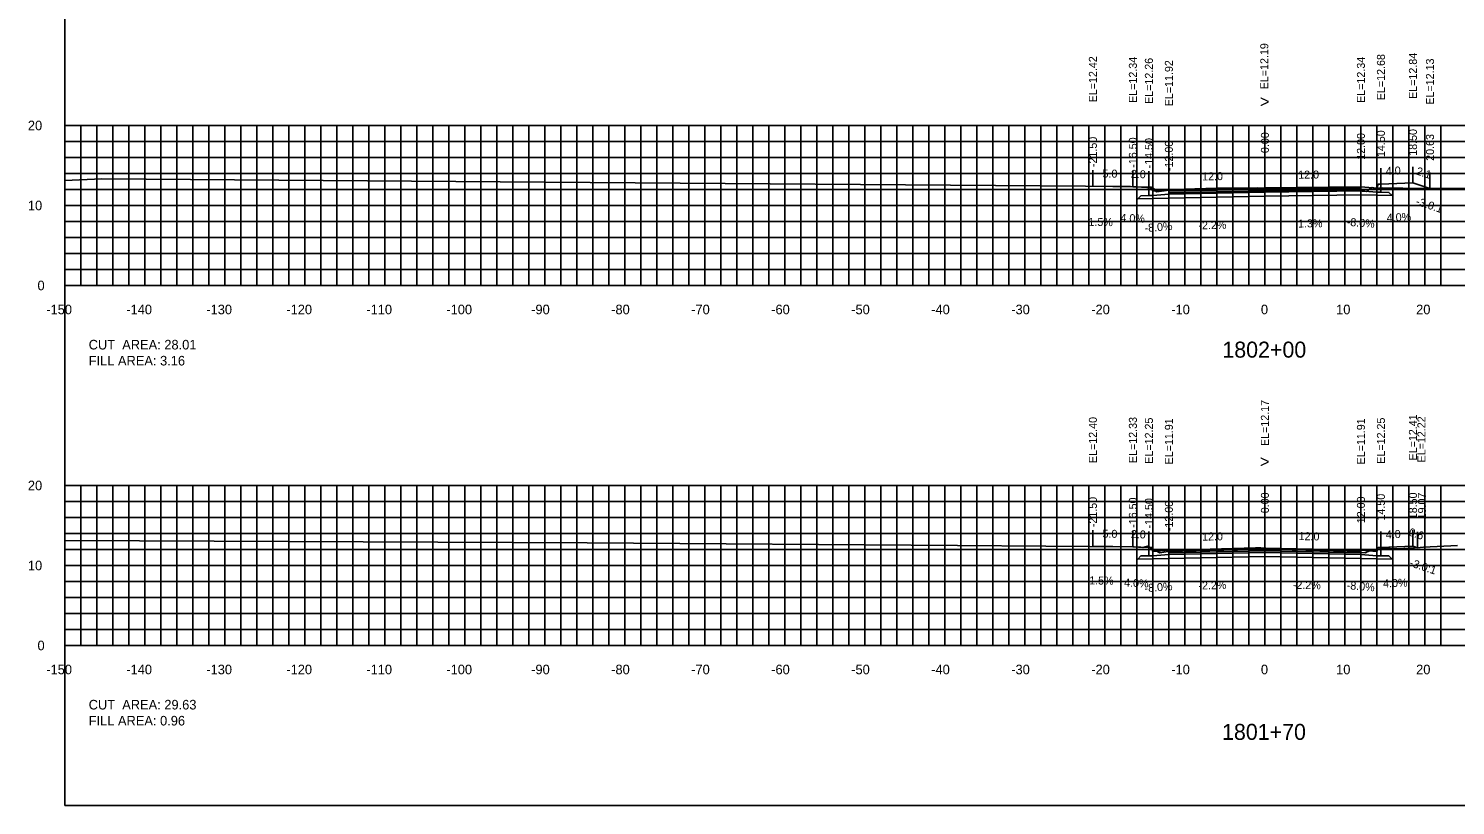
# Model space of a CAD drawing. Extents: x 1797759 to 1802785, y 249826 to 250371.
# Drawn here: x 1802136.5 to 1802314.8, y 250079.4 to 250176.5 of the extents above; entities that cross this region are included whole.
import ezdxf

# ---------------------------------------------------------------- set-up
doc = ezdxf.new("R2010")
doc.units = 0
for name, color, linetype in [('29', 7, 'Continuous'), ('AXIS', 7, 'Continuous'), ('great seal', 7, 'Continuous'), ('Level 1', 7, 'Continuous'), ('Level 10', 7, 'Continuous'), ('Level 13', 7, 'Continuous'), ('Level 15', 7, 'Continuous'), ('Level 30', 7, 'Continuous'), ('Level 40', 7, 'Continuous'), ('Level 45', 7, 'Continuous'), ('Level 63', 7, 'Continuous'), ('Level 7', 7, 'Continuous'), ('LS-SURVEY POINT', 7, 'Continuous'), ('PIPE', 7, 'Continuous'), ('TOPO', 7, 'Continuous')]:
    doc.layers.add(name, color=color, linetype=linetype)

msp = doc.modelspace()

# ---------------------------------------------------------------- linework, layer by layer
at = {"layer": '29'}
for points in [[(1802279, 250156.21), (1802291, 250156.47), (1802303, 250156.62), (1802303, 250156.43), (1802291, 250156.28), (1802279, 250156.02)], [(1802279, 250111.19), (1802291, 250111.45), (1802303, 250111.19), (1802303, 250111), (1802291, 250111.26), (1802279, 250111)]]:
    msp.add_lwpolyline(points, close=True, dxfattribs=at)
at = {"layer": 'AXIS'}
for p, q in [((1802269.5, 250156.85), (1802269.5, 250158.85)), ((1802274.5, 250156.78), (1802274.5, 250158.78)), ((1802276.5, 250156.7), (1802276.5, 250158.7)), ((1802291, 250156.62), (1802291, 250158.62)), ((1802303, 250156.77), (1802303, 250158.77)), ((1802305.5, 250157.11), (1802305.5, 250159.11)), ((1802309.5, 250157.27), (1802309.5, 250159.27)), ((1802311.63, 250156.56), (1802311.63, 250158.56)), ((1802279, 250156.36), (1802279, 250158.36)), ((1802269.5, 250111.83), (1802269.5, 250113.83)), ((1802274.5, 250111.76), (1802274.5, 250113.76)), ((1802276.5, 250111.68), (1802276.5, 250113.68)), ((1802279, 250111.34), (1802279, 250113.34)), ((1802291, 250111.6), (1802291, 250113.6)), ((1802303, 250111.34), (1802303, 250113.34)), ((1802305.5, 250111.68), (1802305.5, 250113.68)), ((1802309.5, 250111.84), (1802309.5, 250113.84)), ((1802310.07, 250111.65), (1802310.07, 250113.65))]:
    msp.add_line(p, q, dxfattribs=at)
for points in [[(1802141, 250079.43), (1802441, 250079.43), (1802441, 250269.43), (1802141, 250269.43)], [(1802303, 250156.77), (1802305, 250156.61), (1802305.17, 250157.11), (1802305.5, 250157.11), (1802305.5, 250156.08), (1802305, 250156.08), (1802303, 250156.24)], [(1802279, 250156.36), (1802277, 250156.2), (1802276.83, 250156.7), (1802276.5, 250156.7), (1802276.5, 250155.67), (1802277, 250155.67), (1802279, 250155.83)], [(1802279, 250111.34), (1802277, 250111.18), (1802276.83, 250111.68), (1802276.5, 250111.68), (1802276.5, 250110.65), (1802277, 250110.65), (1802279, 250110.81)], [(1802303, 250111.34), (1802305, 250111.18), (1802305.17, 250111.68), (1802305.5, 250111.68), (1802305.5, 250110.65), (1802305, 250110.65), (1802303, 250110.81)]]:
    msp.add_lwpolyline(points, close=True, dxfattribs=at)
at = {"layer": 'great seal'}
for points in [[(1802141, 250157.56), (1802145.63, 250157.77), (1802195.44, 250157.4), (1802274.2, 250156.82), (1802275.56, 250156.72), (1802276.24, 250156.66), (1802277.05, 250156.61), (1802277.14, 250156.51), (1802277.45, 250156.13), (1802278.42, 250156.26), (1802279.52, 250156.42), (1802284.96, 250156.58), (1802290.06, 250156.64), (1802302.07, 250156.3), (1802302.17, 250156.3), (1802303.67, 250156.19), (1802303.7, 250156.19), (1802303.77, 250156.24), (1802304.25, 250156.58), (1802304.41, 250156.66), (1802304.86, 250156.61), (1802305.68, 250156.64), (1802310.81, 250156.54), (1802311.15, 250156.54), (1802311.65, 250156.56), (1802319.58, 250156.58)], [(1802141, 250112.56), (1802206.29, 250112.27), (1802252.58, 250111.93), (1802274.67, 250111.77), (1802275.73, 250111.69), (1802276.32, 250111.84), (1802277.86, 250111.03), (1802277.87, 250111.03), (1802277.87, 250111.03), (1802279.89, 250111.33), (1802289.83, 250111.63), (1802290.02, 250111.64), (1802290.48, 250111.62), (1802291.12, 250111.6), (1802302.04, 250111.2), (1802303.09, 250111.06), (1802303.56, 250111.01), (1802303.86, 250111.16), (1802303.92, 250111.19), (1802304.13, 250111.26), (1802304.33, 250111.27), (1802305.51, 250111.52), (1802306.31, 250111.53), (1802306.48, 250111.54), (1802306.67, 250111.54), (1802307.59, 250111.52), (1802307.64, 250111.52), (1802310.4, 250111.67), (1802310.84, 250111.71), (1802315.08, 250111.93)]]:
    msp.add_lwpolyline(points, dxfattribs=at)
at = {"layer": 'Level 1'}
for points in [[(1802269.5, 250156.85), (1802274.5, 250156.78), (1802276.5, 250156.7), (1802276.83, 250156.7), (1802277, 250156.2), (1802279, 250156.36), (1802291, 250156.62), (1802303, 250156.77), (1802305, 250156.61), (1802305.17, 250157.11), (1802305.5, 250157.11), (1802309.5, 250157.27), (1802311.63, 250156.56)], [(1802269.5, 250111.83), (1802274.5, 250111.76), (1802276.5, 250111.68), (1802276.83, 250111.68), (1802277, 250111.18), (1802279, 250111.34), (1802291, 250111.6), (1802303, 250111.34), (1802305, 250111.18), (1802305.17, 250111.68), (1802305.5, 250111.68), (1802309.5, 250111.84), (1802310.07, 250111.65)]]:
    msp.add_lwpolyline(points, dxfattribs=at)
at = {"layer": 'Level 13'}
for points in [[(1802303, 250155.74), (1802306.9, 250155.66), (1802306.5, 250156.06), (1802305.5, 250156.08), (1802305, 250156.08), (1802303, 250156.24), (1802291, 250156.09), (1802279, 250155.83), (1802277, 250155.67), (1802276.5, 250155.67), (1802275.5, 250155.64), (1802275.1, 250155.24), (1802279, 250155.33), (1802291, 250155.59)], [(1802303, 250110.31), (1802306.9, 250110.22), (1802306.5, 250110.63), (1802305.5, 250110.65), (1802305, 250110.65), (1802303, 250110.81), (1802291, 250111.07), (1802279, 250110.81), (1802277, 250110.65), (1802276.5, 250110.65), (1802275.5, 250110.63), (1802275.1, 250110.22), (1802279, 250110.31), (1802291, 250110.57)]]:
    msp.add_lwpolyline(points, close=True, dxfattribs=at)
at = {"layer": 'Level 15'}
for p, q in [((1802141, 250164.43), (1802441, 250164.43)), ((1802141, 250144.43), (1802141, 250164.43)), ((1802143, 250144.43), (1802143, 250164.43)), ((1802145, 250144.43), (1802145, 250164.43)), ((1802147, 250144.43), (1802147, 250164.43)), ((1802149, 250144.43), (1802149, 250164.43)), ((1802151, 250144.43), (1802151, 250164.43)), ((1802153, 250144.43), (1802153, 250164.43)), ((1802155, 250144.43), (1802155, 250164.43)), ((1802157, 250144.43), (1802157, 250164.43)), ((1802159, 250144.43), (1802159, 250164.43)), ((1802161, 250144.43), (1802161, 250164.43)), ((1802163, 250144.43), (1802163, 250164.43)), ((1802165, 250144.43), (1802165, 250164.43)), ((1802167, 250144.43), (1802167, 250164.43)), ((1802169, 250144.43), (1802169, 250164.43)), ((1802171, 250144.43), (1802171, 250164.43)), ((1802173, 250144.43), (1802173, 250164.43)), ((1802175, 250144.43), (1802175, 250164.43)), ((1802177, 250144.43), (1802177, 250164.43)), ((1802179, 250144.43), (1802179, 250164.43)), ((1802181, 250144.43), (1802181, 250164.43)), ((1802183, 250144.43), (1802183, 250164.43)), ((1802185, 250144.43), (1802185, 250164.43)), ((1802187, 250144.43), (1802187, 250164.43)), ((1802189, 250144.43), (1802189, 250164.43)), ((1802191, 250144.43), (1802191, 250164.43)), ((1802193, 250144.43), (1802193, 250164.43)), ((1802195, 250144.43), (1802195, 250164.43)), ((1802197, 250144.43), (1802197, 250164.43)), ((1802199, 250144.43), (1802199, 250164.43)), ((1802201, 250144.43), (1802201, 250164.43)), ((1802203, 250144.43), (1802203, 250164.43)), ((1802205, 250144.43), (1802205, 250164.43)), ((1802207, 250144.43), (1802207, 250164.43)), ((1802209, 250144.43), (1802209, 250164.43)), ((1802211, 250144.43), (1802211, 250164.43)), ((1802213, 250144.43), (1802213, 250164.43)), ((1802215, 250144.43), (1802215, 250164.43)), ((1802217, 250144.43), (1802217, 250164.43)), ((1802219, 250144.43), (1802219, 250164.43)), ((1802221, 250144.43), (1802221, 250164.43)), ((1802223, 250144.43), (1802223, 250164.43)), ((1802225, 250144.43), (1802225, 250164.43)), ((1802227, 250144.43), (1802227, 250164.43)), ((1802229, 250144.43), (1802229, 250164.43)), ((1802231, 250144.43), (1802231, 250164.43)), ((1802233, 250144.43), (1802233, 250164.43)), ((1802235, 250144.43), (1802235, 250164.43)), ((1802237, 250144.43), (1802237, 250164.43)), ((1802239, 250144.43), (1802239, 250164.43)), ((1802241, 250144.43), (1802241, 250164.43)), ((1802243, 250144.43), (1802243, 250164.43)), ((1802245, 250144.43), (1802245, 250164.43)), ((1802247, 250144.43), (1802247, 250164.43)), ((1802249, 250144.43), (1802249, 250164.43)), ((1802251, 250144.43), (1802251, 250164.43)), ((1802253, 250144.43), (1802253, 250164.43)), ((1802255, 250144.43), (1802255, 250164.43)), ((1802257, 250144.43), (1802257, 250164.43)), ((1802259, 250144.43), (1802259, 250164.43)), ((1802261, 250144.43), (1802261, 250164.43)), ((1802263, 250144.43), (1802263, 250164.43)), ((1802265, 250144.43), (1802265, 250164.43)), ((1802267, 250144.43), (1802267, 250164.43)), ((1802269, 250144.43), (1802269, 250164.43)), ((1802271, 250144.43), (1802271, 250164.43)), ((1802273, 250144.43), (1802273, 250164.43)), ((1802275, 250144.43), (1802275, 250164.43)), ((1802277, 250144.43), (1802277, 250164.43)), ((1802279, 250144.43), (1802279, 250164.43)), ((1802281, 250144.43), (1802281, 250164.43)), ((1802283, 250144.43), (1802283, 250164.43)), ((1802285, 250144.43), (1802285, 250164.43)), ((1802287, 250144.43), (1802287, 250164.43)), ((1802289, 250144.43), (1802289, 250164.43)), ((1802291, 250144.43), (1802291, 250164.43)), ((1802293, 250144.43), (1802293, 250164.43)), ((1802295, 250144.43), (1802295, 250164.43)), ((1802297, 250144.43), (1802297, 250164.43)), ((1802299, 250144.43), (1802299, 250164.43)), ((1802301, 250144.43), (1802301, 250164.43)), ((1802303, 250144.43), (1802303, 250164.43)), ((1802305, 250144.43), (1802305, 250164.43)), ((1802307, 250144.43), (1802307, 250164.43)), ((1802309, 250144.43), (1802309, 250164.43)), ((1802311, 250144.43), (1802311, 250164.43)), ((1802313, 250144.43), (1802313, 250164.43)), ((1802141, 250162.43), (1802441, 250162.43)), ((1802141, 250160.43), (1802441, 250160.43)), ((1802141, 250158.43), (1802441, 250158.43)), ((1802141, 250156.43), (1802441, 250156.43)), ((1802141, 250154.43), (1802441, 250154.43)), ((1802141, 250152.43), (1802441, 250152.43)), ((1802141, 250150.43), (1802441, 250150.43)), ((1802141, 250148.43), (1802441, 250148.43)), ((1802141, 250146.43), (1802441, 250146.43)), ((1802141, 250144.43), (1802441, 250144.43)), ((1802141, 250119.43), (1802441, 250119.43)), ((1802141, 250099.43), (1802141, 250119.43)), ((1802143, 250099.43), (1802143, 250119.43)), ((1802145, 250099.43), (1802145, 250119.43)), ((1802147, 250099.43), (1802147, 250119.43)), ((1802149, 250099.43), (1802149, 250119.43)), ((1802151, 250099.43), (1802151, 250119.43)), ((1802153, 250099.43), (1802153, 250119.43)), ((1802155, 250099.43), (1802155, 250119.43)), ((1802157, 250099.43), (1802157, 250119.43)), ((1802159, 250099.43), (1802159, 250119.43)), ((1802161, 250099.43), (1802161, 250119.43)), ((1802163, 250099.43), (1802163, 250119.43)), ((1802165, 250099.43), (1802165, 250119.43)), ((1802167, 250099.43), (1802167, 250119.43)), ((1802169, 250099.43), (1802169, 250119.43)), ((1802171, 250099.43), (1802171, 250119.43)), ((1802173, 250099.43), (1802173, 250119.43)), ((1802175, 250099.43), (1802175, 250119.43)), ((1802177, 250099.43), (1802177, 250119.43)), ((1802179, 250099.43), (1802179, 250119.43)), ((1802181, 250099.43), (1802181, 250119.43)), ((1802183, 250099.43), (1802183, 250119.43)), ((1802185, 250099.43), (1802185, 250119.43)), ((1802187, 250099.43), (1802187, 250119.43)), ((1802189, 250099.43), (1802189, 250119.43)), ((1802191, 250099.43), (1802191, 250119.43)), ((1802193, 250099.43), (1802193, 250119.43)), ((1802195, 250099.43), (1802195, 250119.43)), ((1802197, 250099.43), (1802197, 250119.43)), ((1802199, 250099.43), (1802199, 250119.43)), ((1802201, 250099.43), (1802201, 250119.43)), ((1802203, 250099.43), (1802203, 250119.43)), ((1802205, 250099.43), (1802205, 250119.43)), ((1802207, 250099.43), (1802207, 250119.43)), ((1802209, 250099.43), (1802209, 250119.43)), ((1802211, 250099.43), (1802211, 250119.43)), ((1802213, 250099.43), (1802213, 250119.43)), ((1802215, 250099.43), (1802215, 250119.43)), ((1802217, 250099.43), (1802217, 250119.43)), ((1802219, 250099.43), (1802219, 250119.43)), ((1802221, 250099.43), (1802221, 250119.43)), ((1802223, 250099.43), (1802223, 250119.43)), ((1802225, 250099.43), (1802225, 250119.43)), ((1802227, 250099.43), (1802227, 250119.43)), ((1802229, 250099.43), (1802229, 250119.43)), ((1802231, 250099.43), (1802231, 250119.43)), ((1802233, 250099.43), (1802233, 250119.43)), ((1802235, 250099.43), (1802235, 250119.43)), ((1802237, 250099.43), (1802237, 250119.43)), ((1802239, 250099.43), (1802239, 250119.43)), ((1802241, 250099.43), (1802241, 250119.43)), ((1802243, 250099.43), (1802243, 250119.43)), ((1802245, 250099.43), (1802245, 250119.43)), ((1802247, 250099.43), (1802247, 250119.43)), ((1802249, 250099.43), (1802249, 250119.43)), ((1802251, 250099.43), (1802251, 250119.43)), ((1802253, 250099.43), (1802253, 250119.43)), ((1802255, 250099.43), (1802255, 250119.43)), ((1802257, 250099.43), (1802257, 250119.43)), ((1802259, 250099.43), (1802259, 250119.43)), ((1802261, 250099.43), (1802261, 250119.43)), ((1802263, 250099.43), (1802263, 250119.43)), ((1802265, 250099.43), (1802265, 250119.43)), ((1802267, 250099.43), (1802267, 250119.43)), ((1802269, 250099.43), (1802269, 250119.43)), ((1802271, 250099.43), (1802271, 250119.43)), ((1802273, 250099.43), (1802273, 250119.43)), ((1802275, 250099.43), (1802275, 250119.43)), ((1802277, 250099.43), (1802277, 250119.43)), ((1802279, 250099.43), (1802279, 250119.43)), ((1802281, 250099.43), (1802281, 250119.43)), ((1802283, 250099.43), (1802283, 250119.43)), ((1802285, 250099.43), (1802285, 250119.43)), ((1802287, 250099.43), (1802287, 250119.43)), ((1802289, 250099.43), (1802289, 250119.43)), ((1802291, 250099.43), (1802291, 250119.43)), ((1802293, 250099.43), (1802293, 250119.43)), ((1802295, 250099.43), (1802295, 250119.43)), ((1802297, 250099.43), (1802297, 250119.43)), ((1802299, 250099.43), (1802299, 250119.43)), ((1802301, 250099.43), (1802301, 250119.43)), ((1802303, 250099.43), (1802303, 250119.43)), ((1802305, 250099.43), (1802305, 250119.43)), ((1802307, 250099.43), (1802307, 250119.43)), ((1802309, 250099.43), (1802309, 250119.43)), ((1802311, 250099.43), (1802311, 250119.43)), ((1802313, 250099.43), (1802313, 250119.43)), ((1802141, 250117.43), (1802441, 250117.43)), ((1802141, 250115.43), (1802441, 250115.43)), ((1802141, 250113.43), (1802441, 250113.43)), ((1802141, 250111.43), (1802441, 250111.43)), ((1802141, 250109.43), (1802441, 250109.43)), ((1802141, 250107.43), (1802441, 250107.43)), ((1802141, 250105.43), (1802441, 250105.43)), ((1802141, 250103.43), (1802441, 250103.43)), ((1802141, 250101.43), (1802441, 250101.43)), ((1802141, 250099.43), (1802441, 250099.43))]:
    msp.add_line(p, q, dxfattribs=at)
at = {"layer": 'Level 30'}
for p, q in [((1802140.94, 250164.43), (1802141, 250164.43)), ((1802141, 250144.43), (1802141, 250164.43)), ((1802140.94, 250154.43), (1802141, 250154.43)), ((1802140.94, 250144.43), (1802141, 250144.43)), ((1802141, 250144.43), (1802441, 250144.43)), ((1802141, 250144.37), (1802141, 250144.43)), ((1802151, 250144.37), (1802151, 250144.43)), ((1802161, 250144.37), (1802161, 250144.43)), ((1802171, 250144.37), (1802171, 250144.43)), ((1802181, 250144.37), (1802181, 250144.43)), ((1802191, 250144.37), (1802191, 250144.43)), ((1802201, 250144.37), (1802201, 250144.43)), ((1802211, 250144.37), (1802211, 250144.43)), ((1802221, 250144.37), (1802221, 250144.43)), ((1802231, 250144.37), (1802231, 250144.43)), ((1802241, 250144.37), (1802241, 250144.43)), ((1802251, 250144.37), (1802251, 250144.43)), ((1802261, 250144.37), (1802261, 250144.43)), ((1802271, 250144.37), (1802271, 250144.43)), ((1802281, 250144.37), (1802281, 250144.43)), ((1802291, 250144.37), (1802291, 250144.43)), ((1802301, 250144.37), (1802301, 250144.43)), ((1802311, 250144.37), (1802311, 250144.43)), ((1802140.94, 250119.43), (1802141, 250119.43)), ((1802141, 250099.43), (1802141, 250119.43)), ((1802140.94, 250109.43), (1802141, 250109.43)), ((1802140.94, 250099.43), (1802141, 250099.43)), ((1802141, 250099.43), (1802441, 250099.43)), ((1802141, 250099.37), (1802141, 250099.43)), ((1802151, 250099.37), (1802151, 250099.43)), ((1802161, 250099.37), (1802161, 250099.43)), ((1802171, 250099.37), (1802171, 250099.43)), ((1802181, 250099.37), (1802181, 250099.43)), ((1802191, 250099.37), (1802191, 250099.43)), ((1802201, 250099.37), (1802201, 250099.43)), ((1802211, 250099.37), (1802211, 250099.43)), ((1802221, 250099.37), (1802221, 250099.43)), ((1802231, 250099.37), (1802231, 250099.43)), ((1802241, 250099.37), (1802241, 250099.43)), ((1802251, 250099.37), (1802251, 250099.43)), ((1802261, 250099.37), (1802261, 250099.43)), ((1802271, 250099.37), (1802271, 250099.43)), ((1802281, 250099.37), (1802281, 250099.43)), ((1802291, 250099.37), (1802291, 250099.43)), ((1802301, 250099.37), (1802301, 250099.43)), ((1802311, 250099.37), (1802311, 250099.43))]:
    msp.add_line(p, q, dxfattribs=at)
at = {"layer": 'PIPE'}
for points in [[(1802279, 250155.83), (1802279, 250156.02), (1802291, 250156.28), (1802303, 250156.43), (1802303, 250156.24), (1802291, 250156.09)], [(1802279, 250110.81), (1802279, 250111), (1802291, 250111.26), (1802303, 250111), (1802303, 250110.81), (1802291, 250111.07)]]:
    msp.add_lwpolyline(points, close=True, dxfattribs=at)
at = {"layer": 'TOPO'}
for points in [[(1802303, 250156.62), (1802303, 250156.77), (1802291, 250156.62), (1802279, 250156.36), (1802279, 250156.21), (1802291, 250156.47)], [(1802303, 250111.19), (1802303, 250111.34), (1802291, 250111.6), (1802279, 250111.34), (1802279, 250111.19), (1802291, 250111.45)]]:
    msp.add_lwpolyline(points, close=True, dxfattribs=at)

# ---------------------------------------------------------------- texts
at = {"layer": 'AXIS'}
for p in [(1802309.78, 250154.55), (1802308.99, 250109.37)]:
    msp.add_text('-3.0:1', height=1, rotation=341.5651, dxfattribs=at).set_placement(p)
at = {"layer": 'Level 10'}
for s, p in [('1802+00', (1802285.68, 250135.41)), ('1801+70', (1802285.64, 250087.63))]:
    msp.add_text(s, height=2, dxfattribs=at).set_placement(p)
at = {"layer": 'Level 30'}
for s, height, p in [('>', 1.5, (1802290.39, 250166.68)), ('-', 0.0001, (1802141, 250144.43)), ('>', 1.5, (1802290.39, 250121.68)), ('-', 0.0001, (1802141, 250099.43))]:
    msp.add_text(s, height=height, dxfattribs=at).set_placement(p)
at = {"layer": 'Level 40'}
for s, p in [('EL=12.19', (1802291.42, 250168.95)), ('EL=12.42', (1802270, 250167.32)), ('EL=12.34', (1802275, 250167.25)), ('EL=12.26', (1802277, 250167.12)), ('EL=12.34', (1802303.5, 250167.25)), ('EL=12.68', (1802306, 250167.59)), ('EL=12.84', (1802310, 250167.75)), ('EL=11.92', (1802279.5, 250166.83)), ('EL=12.13', (1802312.13, 250167.03)), ('18.50', (1802310, 250160.64)), ('-21.50', (1802270, 250159.23)), ('-16.50', (1802275, 250159.15)), ('-14.50', (1802277, 250159.07)), ('-12.00', (1802279.5, 250158.73)), ('0.00', (1802291.5, 250160.98)), ('12.00', (1802303.5, 250160.14)), ('14.50', (1802306, 250160.48)), ('20.63', (1802312.13, 250160.01)), ('EL=12.17', (1802291.5, 250124.36)), ('EL=12.41', (1802310, 250122.56)), ('EL=12.40', (1802270, 250122.23)), ('EL=12.33', (1802275, 250122.23)), ('EL=12.25', (1802277, 250122.15)), ('EL=11.91', (1802279.5, 250122.06)), ('EL=11.91', (1802303.5, 250122.06)), ('EL=12.25', (1802306, 250122.15)), ('EL=12.22', (1802311.06, 250122.31)), ('-21.50', (1802270, 250114.21)), ('-16.50', (1802275, 250114.14)), ('-14.50', (1802277, 250114.06)), ('0.00', (1802291.5, 250115.96)), ('12.00', (1802303.5, 250114.71)), ('14.50', (1802306, 250115.05)), ('18.50', (1802310, 250115.21)), ('19.07', (1802311.12, 250115.19)), ('-12.00', (1802279.5, 250113.72))]:
    msp.add_text(s, height=1, rotation=90, dxfattribs=at).set_placement(p)
at = {"layer": 'Level 45'}
for s, p in [('-150', (1802138.7, 250140.83)), ('-140', (1802148.7, 250140.83)), ('-130', (1802158.7, 250140.83)), ('-120', (1802168.7, 250140.83)), ('-110', (1802178.7, 250140.83)), ('-100', (1802188.7, 250140.83)), ('-90', (1802199.3, 250140.83)), ('-80', (1802209.3, 250140.83)), ('-70', (1802219.3, 250140.83)), ('-60', (1802229.3, 250140.83)), ('-50', (1802239.3, 250140.83)), ('-40', (1802249.3, 250140.83)), ('-30', (1802259.3, 250140.83)), ('-20', (1802269.3, 250140.83)), ('-10', (1802279.3, 250140.83)), ('0', (1802290.5, 250140.83)), ('10', (1802299.9, 250140.83)), ('20', (1802309.9, 250140.83)), ('-150', (1802138.7, 250095.83)), ('-140', (1802148.7, 250095.83)), ('-130', (1802158.7, 250095.83)), ('-120', (1802168.7, 250095.83)), ('-110', (1802178.7, 250095.83)), ('-100', (1802188.7, 250095.83)), ('-90', (1802199.3, 250095.83)), ('-80', (1802209.3, 250095.83)), ('-70', (1802219.3, 250095.83)), ('-60', (1802229.3, 250095.83)), ('-50', (1802239.3, 250095.83)), ('-40', (1802249.3, 250095.83)), ('-30', (1802259.3, 250095.83)), ('-20', (1802269.3, 250095.83)), ('-10', (1802279.3, 250095.83)), ('0', (1802290.5, 250095.83)), ('10', (1802299.9, 250095.83)), ('20', (1802309.9, 250095.83))]:
    msp.add_text(s, height=1.2, dxfattribs=at).set_placement(p)
at = {"layer": 'Level 63'}
for s, rotation, p in [('5.0', 359.1406, (1802270.7, 250157.93)), ('2.0', 357.7094, (1802274.23, 250157.89)), ('12.0', 1.2603, (1802283.16, 250157.55)), ('12.0', 0.7297, (1802295.17, 250157.77)), ('4.0', 2.2906, (1802306.13, 250158.24)), ('2.1', 341.5651, (1802309.82, 250158.33)), ('4.0%', 357.7094, (1802272.93, 250152.4)), ('4.0%', 2.2906, (1802306.25, 250152.4)), ('1.5%', 359.1406, (1802268.94, 250151.89)), ('-8.0%', 4.5739, (1802276, 250151.1)), ('-2.2%', 1.2603, (1802282.7, 250151.44)), ('1.3%', 0.7297, (1802295.15, 250151.67)), ('-8.0%', 355.4261, (1802301.2, 250151.9)), ('0.6', 341.5651, (1802308.89, 250113.2)), ('5.0', 359.1406, (1802270.7, 250112.91)), ('2.0', 357.7094, (1802274.23, 250112.87)), ('12.0', 1.2603, (1802283.16, 250112.53)), ('12.0', 358.7397, (1802295.21, 250112.61)), ('4.0', 2.2906, (1802306.13, 250112.8)), ('1.5%', 359.1406, (1802269.03, 250107.07)), ('4.0%', 357.7094, (1802273.39, 250106.8)), ('-8.0%', 4.5739, (1802276, 250106.08)), ('-2.2%', 1.2603, (1802282.7, 250106.42)), ('-2.2%', 358.7397, (1802294.48, 250106.52)), ('-8.0%', 355.4261, (1802301.2, 250106.47)), ('4.0%', 2.2906, (1802305.79, 250106.68))]:
    msp.add_text(s, height=1, rotation=rotation, dxfattribs=at).set_placement(p)
at = {"layer": 'Level 7'}
for s, p in [('20', (1802136.4, 250163.83)), ('10', (1802136.4, 250153.83)), ('0', (1802137.6, 250143.83)), ('20', (1802136.4, 250118.83)), ('10', (1802136.4, 250108.83)), ('0', (1802137.6, 250098.83))]:
    msp.add_text(s, height=1.2, dxfattribs=at).set_placement(p)
at = {"layer": 'LS-SURVEY POINT'}
for s, p in [('CUT  AREA: 28.01', (1802144, 250136.43)), ('FILL AREA: 3.16', (1802144, 250134.43)), ('CUT  AREA: 29.63', (1802144, 250091.43)), ('FILL AREA: 0.96', (1802144, 250089.43))]:
    msp.add_text(s, height=1.2, dxfattribs=at).set_placement(p)

doc.saveas('drawing.dxf')
